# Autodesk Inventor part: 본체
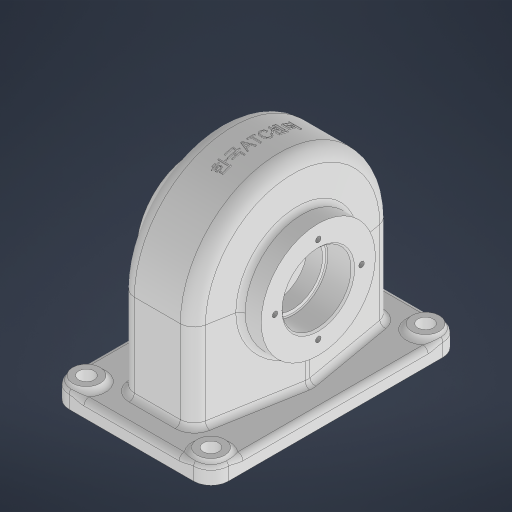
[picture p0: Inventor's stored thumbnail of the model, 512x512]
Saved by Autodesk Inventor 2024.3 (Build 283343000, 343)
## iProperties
Created: 2025-05
Part Number: 본체
Material: 일반
Document SubType Name: Modeling
Designer: user
Density: 1 g/cm^3
Appearance: 기본값
Author: user
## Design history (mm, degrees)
sketch "스케치1"
  geometry: L1 (0, 30.051)-(0, -30.051); L2 (0, 30.051)-(57, 20); L3 (57, 20)-(57, -20); L4 (57, -20)-(0, -30.051); 2 further points
  constraints: 8 end point, 2 vertical, 1 coincident, 1 equal length, 1 midpoint
  dimensions: "d4" = 20 deg angle of L2 L4; "d5" = 40 distance of L2.end L3.end; "d6" = 114 diameter of L3 L1
revolve "회전1" sketch "스케치1" stored, may be unused: angle "d0" = 180 deg
sketch "스케치2"
  geometry: L1 (0, 40)-(57, 50.051) reference; L2 (0, 0)-(0, 40) reference; L3 (57, -10.051)-(0, 0) reference; L4 (57, -10.051)-(114, 0) reference; L5 (114, 0)-(114, 40) reference; L6 (114, 40)-(57, 50.051) reference; 1 further point
extrude "돌출1" join sketch "스케치2" distance "d1" = 60; taper "d2" = 0 deg
fillet "모깎기1" dims "d7" = 8
feature "쉘1" dims "d3" = 5
sketch "스케치3"
  geometry: L1 (-15, -26)-(129, -26); L2 (129, -26)-(129, 66); L3 (129, 66)-(-15, 66); L4 (-15, 66)-(-15, -26); L5 (-15, -26)-(129, 66); L6 (129, -26)-(-15, 66); 1 further point
  constraints: 12 end point, 2 midpoint, 2 parallel, 1 horizontal, 1 perpendicular
  dimensions: "d8" = 144 distance of L2.end L3.end; "d9" = 92 distance between parallel lines of L3 L1
extrude "돌출2" join sketch "스케치3" distance "d10" = 9; taper "d11" = 0 deg
fillet "모깎기2" dims "d12" = 10
sketch "스케치4"
  geometry: C1 r 8 at (-119, -16); C2 r 8 at (5, -16); A1 r 10 centre (-119, -16) between (-129, -16) and (-119, -26) reference; A2 r 10 centre (5, -16) between (5, -26) and (15, -16) reference; 3 further points
  constraints: 2 centre point, 2 coincident
  dimensions: "d13" = 16 diameter of C1; "d14" = 16 diameter of C2
extrude "돌출3" join sketch "스케치4" distance "d15" = 3; taper "d16" = 0 deg
sketch "스케치5"
  geometry: C1 r 8 at (0, 0) reference; 2 further points
  constraints: 1 coincident
hole "구멍1" sketch "스케치5" at (0, 0) diameter "d17" = 9; stored, may be unused: countersink angle "d21" = 90 deg, drill point angle "d23" = 118 deg; dims "d18" = 6, "d19" = 4, "d20" = 2, "d22" = 8
sketch "스케치6"
  geometry: C1 r 8 at (0, 0) reference; 2 further points
  constraints: 1 coincident
hole "구멍2" sketch "스케치6" at (0, 0) diameter "d24" = 9; stored, may be unused: countersink angle "d28" = 90 deg, drill point angle "d30" = 118 deg; dims "d25" = 6, "d26" = 4, "d27" = 2, "d29" = 8
node "작업 평면1"
sketch "스케치8"
  geometry: C1 r 24 at (0, 0); 1 further point
  constraints: 1 centre point, 1 coincident
  dimensions: "d32" = 48 diameter of C1
extrude "돌출4" join sketch "스케치8" stored distance "d33" = 3; taper "d34" = 0 deg
node "작업 평면2"
sketch "스케치9"
  geometry: C1 r 33 at (0, 0); 1 further point
  constraints: 1 centre point, 1 coincident
  dimensions: "d36" = 66 diameter of C1
extrude "돌출5" join sketch "스케치9" stored distance "d37" = 10; taper "d38" = 0 deg
sketch "스케치10"
  geometry: C1 r 33 at (0, 0) reference; 2 further points
  constraints: 1 coincident
hole "구멍3" sketch "스케치10" at (0, 0) diameter "d39" = 35; stored, may be unused: countersink angle "d43" = 90 deg, drill point angle "d45" = 0 deg; dims "d40" = 6, "d41" = 40, "d42" = 15, "d44" = 8
sketch "스케치11"
  geometry: L1 (0, 0)-(0, -25); C1 r 33 at (0, 0) reference; 1 further point
  constraints: 2 end point, 1 coincident, 1 vertical
  dimensions: "d46" = 25 distance of L1.start L1.end
hole "구멍4" sketch "스케치11" at (0, -25) diameter "d47" = 3.242; stored, may be unused: countersink angle "d51" = 90 deg, drill point angle "d53" = 118 deg; dims "d48" = 8, "d49" = 40, "d50" = 15, "d52" = 10
fillet "모깎기3" dims "d57" = 3
fillet "모깎기4" dims "d58" = 3
chamfer "모따기1" distance "d59" = 1; stored, may be unused: second distance "d60" = 2, angle "d61" = 45 deg
fillet "모깎기5" dims "d62" = 3
fillet "모깎기6" dims "d63" = 0.6
node "작업 평면4"
sketch "스케치12" dims "d4" = 20 deg, "d5" = 40, "d6" = 114
  geometry: 2 further points
  constraints: 1 coincident, 1 other
feature "엠보싱1" sketch "스케치12" dims "d66" = 0.5, "d67" = 0
sketch "스케치13"
  geometry: L1 (-5, 33.287)-(-5, 6.713) reference; L2 (-56.479, 44.882)-(-7.479, 36.242) reference; L3 (-106.521, 36.242)-(-57.521, 44.882) reference; L4 (-109, 6.713)-(-109, 33.287) reference; L5 (-57.521, -4.882)-(-106.521, 3.758) reference; L6 (-7.479, 3.758)-(-56.479, -4.882) reference; A1 r 3 centre (-8, 6.713) between (-7.479, 3.758) and (-5, 6.713) reference; A2 r 3 centre (-8, 33.287) between (-5, 33.287) and (-7.479, 36.242) reference; A3 r 3 centre (-57, 41.927) between (-56.479, 44.882) and (-57.521, 44.882) reference; A4 r 3 centre (-106, 33.287) between (-106.521, 36.242) and (-109, 33.287) reference; A5 r 3 centre (-106, 6.713) between (-109, 6.713) and (-106.521, 3.758) reference; A6 r 3 centre (-57, -1.927) between (-57.521, -4.882) and (-56.479, -4.882) reference; 1 further point
extrude "돌출6" cut sketch "스케치13" extent not by distance; stored distance "d68" = 0; taper "d69" = 0 deg
fillet "모깎기7" dims "d70" = 3
feature "ˁ耀˃耀˅耀ˇ耀ˉ耀ˋ耀ˍ耀ˏ耀" dims "d0" = 180 deg, "d1" = 60, "d2" = 0, "d3" = 5, "d4" = 20 deg, "d5" = 40, "d6" = 114, "d7" = 8, "d8" = 144, "d9" = 92, "d10" = 9, "d11" = 0, "d12" = 10, "d13" = 16, "d14" = 16, "d15" = 3, "d16" = 0, "d17" = 9, "d18" = 6, "d19" = 4, "d20" = 2, "d21" = 90 deg, "d22" = 8, "d23" = 118 deg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
node "솔리드1"
mirror "미러1"
mirror "미러2"
pattern_circular "원형 패턴1" dims angle "d55" = 360 deg
mirror "미러3"
feature "A9D066F2-1C7D-4E18-AEED-F7BC21143FA4" dims "d17" = 9, "d18" = 6, "d19" = 4, "d20" = 2, "d21" = 90 deg, "d22" = 8, "d23" = 118 deg
